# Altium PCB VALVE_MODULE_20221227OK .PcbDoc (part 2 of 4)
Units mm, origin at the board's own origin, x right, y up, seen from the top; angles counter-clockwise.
Board outline 260.15 x 142.01 mm, 2 copper layers (Top Layer, Bottom Layer); 455 components, 212 nets, 1302 pads, 385 vias.
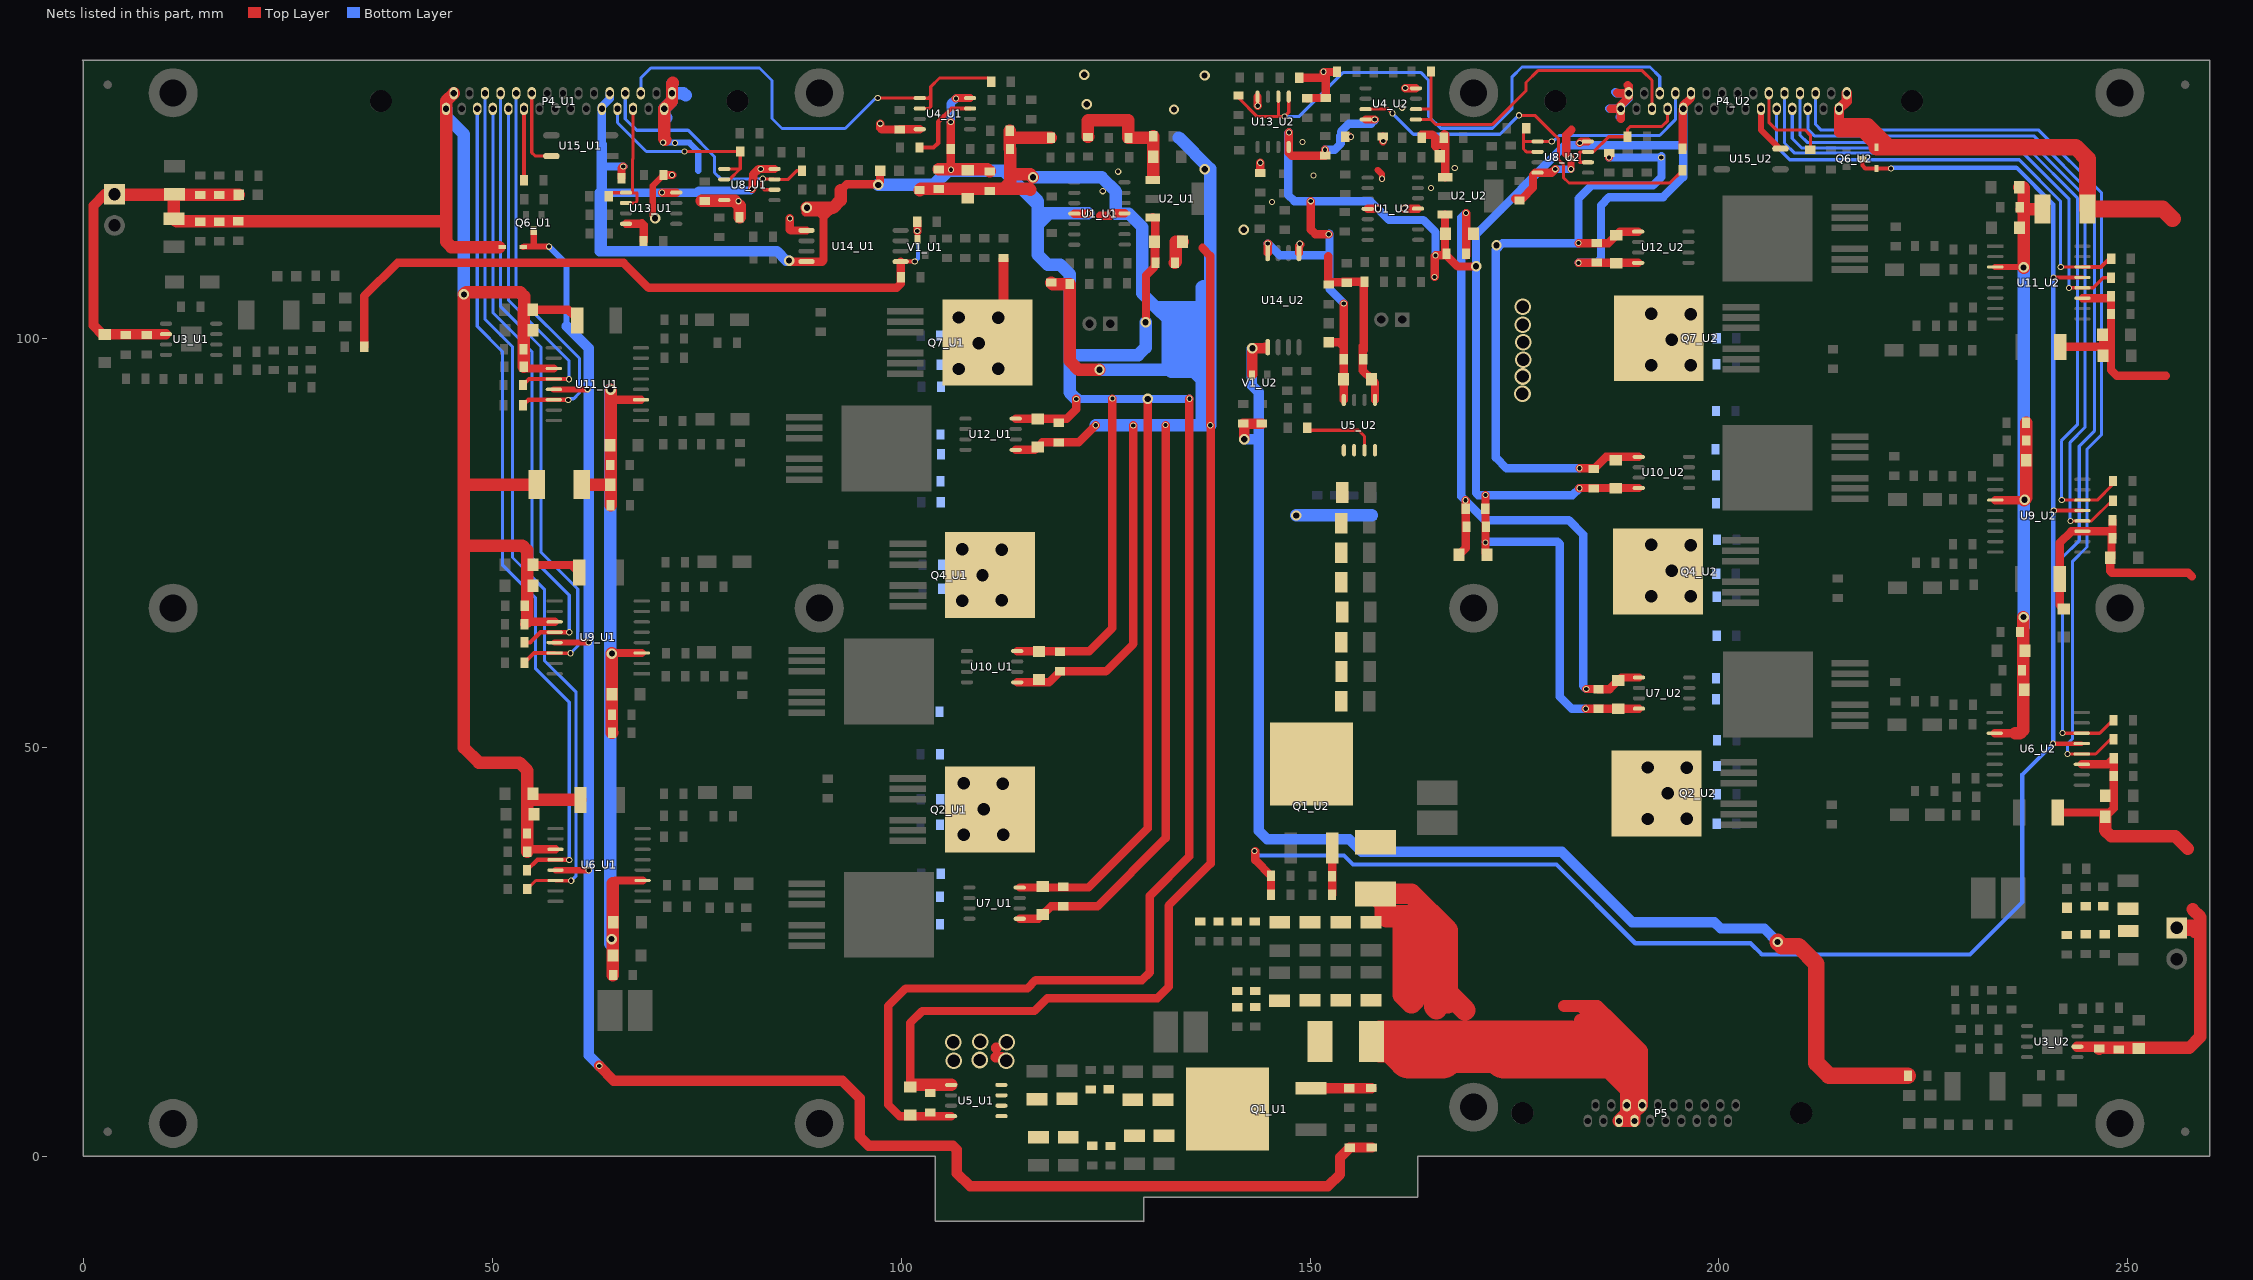
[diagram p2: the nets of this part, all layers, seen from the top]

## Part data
C1_U1 C1_U2 C2_U1 C2_U2: library part ELECTRO1, "Electrolytic Capacitor"
C3_U1 C3_U2 C4_U1 C4_U2 C12_U1 C12_U2 C14_U1 C14_U2 C31_U1 C31_U2 C32_U1 C32_U2 C33_U1 C33_U2 C42_U1 C42_U2 C43_U1 C43_U2 C44_U1 C44_U2 C45_U1 C45_U2 C46_U1 C46_U2 C48_U1 C48_U2 C50_U1 C50_U2 C51_U1 C51_U2 C52_U1 C52_U2 C53_U1 C53_U2 C61_U1 C61_U2 C64_U1 C64_U2 C67_U1 C67_U2 C68_U1 C68_U2 C73_U1 C73_U2 C74_U1 C74_U2 C75_U1 C75_U2 C76_U1 C76_U2 C77_U1 C77_U2 C78_U1 C78_U2 C79_U1 C79_U2 C80_U1 C80_U2 C81_U1 C81_U2 C82_U1 C82_U2 C83_U1 C83_U2 C84_U1 C84_U2 C85_U1 C85_U2 C86_U1 C86_U2 C87_U1 C87_U2 C88_U1 C88_U2 C89_U1 C89_U2 C90_U1 C90_U2 C91_U1 C91_U2 C92_U1 C92_U2 C93_U1 C93_U2 C95 C96 C97 C98 C99 C100 C101 C102 C103_U1 C103_U2 C107_U1 C107_U2 C109_U1 C109_U2 C111_U1 C111_U2 C113_U1 C113_U2: library part CAP, "Capacitor"
C5_U1 C5_U2 C6_U1 C6_U2 C24_U1 C24_U2 C41_U1 C41_U2 C49_U1 C49_U2 C55_U1 C55_U2 C56_U1 C56_U2 C57_U1 C57_U2 C66_U1 C66_U2 C72_U1 C72_U2 C104_U1 C104_U2 C106_U1 C106_U2 C108_U1 C108_U2 C110_U1 C110_U2 C112_U1 C112_U2: library part Cap2, "Capacitor"
C7_U1 C7_U2 C8_U1 C8_U2 C9_U1 C9_U2 C10_U1 C10_U2 C11_U1 C11_U2 C13_U1 C13_U2 C23_U1 C23_U2 C25_U1 C25_U2 C29_U1 C29_U2 C30_U1 C30_U2 C58_U1 C58_U2 C59_U1 C59_U2 C60_U1 C60_U2 C69_U1 C69_U2 C105_U1 C105_U2: library part "Cap Semi", "Capacitor (Semiconductor SIM Model)"
C15_U1 C15_U2 C16_U1 C16_U2 C17_U1 C17_U2 C18_U1 C18_U2 C19_U1 C19_U2 C20_U1 C20_U2 C34 C35 C36 C37 C38 C39 C40 C70_U1 C70_U2 C71_U1 C71_U2 C94: library part "Cap Pol1", "Polarized Capacitor (Radial)"
C21_U1 C21_U2 C22_U1 C22_U2 C65_U1 C65_U2: library part CAP1
C26_U1 C26_U2 C27_U1 C27_U2 C28_U1 C28_U2: library part Cap, "Capacitor"
C47_U1 C47_U2 C54_U1 C54_U2: "Capacitor (Semiconductor SIM Model)"
C62_U1 C62_U2 C63_U1 C63_U2: library part CAP
D1_U1 D1_U2: library part LED2
D2_U1 D2_U2 D5_U1 D5_U2 D9_U1 D9_U2 D10_U1 D10_U2 D14_U1 D14_U2 D15_U1 D15_U2 D18_U1 D18_U2: library part "DIODE SCHOTTKY", "Schottky Diode"
D3_U1 D3_U2 D19_U1 D19_U2: library part LED0, "Typical INFRARED GaAs LED"
D6_U1 D6_U2 D8_U1 D8_U2 D11_U1 D11_U2 D16_U1 D16_U2: library part Diode, "Default Diode"
F1 F2: library part "Fuse 2", "Fuse"
L1_U1 L1_U2 L2_U1 L2_U2: library part Inductor, "Inductor"
P1_U1 P1_U2 P2_U1 P2_U2: "Header, 2-Pin"
P4_U1 P4_U2: "Header, 15-Pin, Dual row"
P5: "Header, 10-Pin, Dual row"
Q1_U1 Q1_U2: library part MOSFET-P, "P-Channel MOSFET"
Q2_U1 Q2_U2 Q3_U1 Q3_U2 Q4_U1 Q4_U2 Q5_U1 Q5_U2 Q7_U1 Q7_U2 Q8_U1 Q8_U2: library part IPB160N04S3-H2
R1_U1 R1_U2 R2_U1 R2_U2 R3_U1 R3_U2 R4_U1 R4_U2 R5_U1 R5_U2 R6_U1 R6_U2 R7_U1 R7_U2 R8_U1 R8_U2 R9_U1 R9_U2 R10_U1 R10_U2 R11_U1 R11_U2 R12_U1 R12_U2 R13_U1 R13_U2 R14_U1 R14_U2 R15_U1 R15_U2 R18_U1 R18_U2 R21_U1 R21_U2 R23_U1 R23_U2 R26_U1 R26_U2 R27_U1 R27_U2 R28_U1 R28_U2 R29_U1 R29_U2 R30_U1 R30_U2 R32_U1 R32_U2 R34_U1 R34_U2 R35_U1 R35_U2 R36_U1 R36_U2 R37_U1 R37_U2 R38_U1 R38_U2 R39_U1 R39_U2 R41_U1 R41_U2 R42_U1 R42_U2 R43_U1 R43_U2 R44_U1 R44_U2 R47_U1 R47_U2 R49_U1 R49_U2 R52_U1 R52_U2 R53_U1 R53_U2 R54_U1 R54_U2 R56_U1 R56_U2 R57_U1 R57_U2 R59_U1 R59_U2 R60_U1 R60_U2 R61_U1 R61_U2 R62_U1 R62_U2 R64_U1 R64_U2 R66_U1 R66_U2 R67_U1 R67_U2 R68_U1 R68_U2 R69_U1 R69_U2 R70_U1 R70_U2 R72_U1 R72_U2 R73_U1 R73_U2 R74_U1 R74_U2 R75_U1 R75_U2 R76_U1 R76_U2 R77_U1 R77_U2 R78_U1 R78_U2 R79 R80: library part Res2, "Resistor"
R16_U1 R16_U2 R17_U1 R17_U2 R19_U1 R19_U2 R20_U1 R20_U2 R22_U1 R22_U2 R24_U1 R24_U2 R25_U1 R25_U2 R31_U1 R31_U2 R33_U1 R33_U2 R40_U1 R40_U2 R45_U1 R45_U2 R46_U1 R46_U2 R48_U1 R48_U2 R50_U1 R50_U2 R55_U1 R55_U2 R58_U1 R58_U2 R63_U1 R63_U2 R65_U1 R65_U2 R71_U1 R71_U2: library part RES
U1_U1 U1_U2: library part TL084D, "JFET-Input Operational Amplifier"
U2_U1 U2_U2: library part AS1117
U4_U1 U4_U2 U8_U1 U8_U2 U13_U1 U13_U2: library part LT1358, "Fast Settling Dual Operational Amplifier"
U5_U1 U5_U2 U7_U1 U7_U2 U10_U1 U10_U2 U12_U1 U12_U2: library part ACS711
U15_U1 U15_U2: library part TLP521-1

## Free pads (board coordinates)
  round 1.016 smd: ""(3,3) ""(3,131) ""(257,3) ""(257,131)
  round 1.016 smd far side: ""(3,3) ""(3,131) ""(257,3) ""(257,131)
  round 6 hole 3.3: ""(11,4) ""(11,67) ""(11,130) ""(90,4) ""(90,67) ""(90,130) ""(170,6) ""(170,67) ""(170,130) ""(249,4) ""(249,67) ""(249,130)

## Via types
v1: diameter 0.762, hole 0.508, Top Layer to Bottom Layer, 142 vias
v2: diameter 2.032, hole 1.524, Top Layer to Bottom Layer, 140 vias
v3: diameter 1.27, hole 0.762, Top Layer to Bottom Layer, 77 vias
v4: diameter 1.27, hole 0.711, Top Layer to Bottom Layer, 14 vias
v5: diameter 1.778, hole 1.27, Top Layer to Bottom Layer, 12 vias

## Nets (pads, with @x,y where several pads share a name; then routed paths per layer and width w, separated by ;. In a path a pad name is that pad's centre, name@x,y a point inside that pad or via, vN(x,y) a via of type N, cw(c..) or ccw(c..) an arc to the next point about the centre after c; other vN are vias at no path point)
1PWM1_U1: P4_U1.3 R31_U1.1 U6_U1.12 | length 102.2
  Top Layer w0.508: R31_U1.1@54.28,34.976 55.55,36.246 U6_U1.12@57.752,36.246 59.461,36.246 v1(59.436,36.22)
  Bottom Layer w0.381: P4_U1.3@48.184,128.047 48.184,101.447 51.257,98.374 51.257,72.314 55.296,68.275 55.296,59.639 59.436,55.499 v1(59.436,36.22)
1PWM1_U2: P4_U2.3 R31_U2.1 U6_U2.12 | length 118.9
  Top Layer w0.381: v1(242.621,49.174) U6_U2.12@244.355,49.174 246.05,49.174 247.828,50.952 R31_U2.1@248.234,50.952
  Bottom Layer w0.381: P4_U2.3@211.813,129.952 211.813,126.134 212.496,125.451 239.09,125.451 246.786,117.754 246.786,88.24 244.983,86.436 244.983,74.473 243.205,72.695 243.205,51.003 242.621,50.419 v1(242.621,49.174)
1PWM2_U1: P4_U1.18 R33_U1.1 U6_U1.14 | length 106.9
  Top Layer w0.381: R33_U1.1@54.305,32.664 55.347,33.706 U6_U1.14@57.752,33.706 57.778,33.68 v1(59.665,33.68)
  Bottom Layer w0.381: P4_U1.18@49.136,129.952 49.137,102.324 52.502,98.958 52.502,73.203 56.388,69.317 56.388,60.604 60.274,56.718 60.274,34.29 v1(59.665,33.68)
1PWM2_U2: P4_U2.18 R33_U2.1 U6_U2.14 | length 115.1
  Top Layer w0.381: v1(241.986,51.74) 242.011,51.714 U6_U2.14@244.355,51.714 246.532,51.714 248.133,53.315 R33_U2.1@248.234,53.315
  Bottom Layer w0.381: P4_U2.18@210.861,128.047 210.861,125.537 211.658,124.739 238.481,124.739 245.897,117.323 245.897,88.646 244.043,86.792 244.043,75.26 241.986,73.203 v1(241.986,51.74)
1PWM3_U1: P4_U1.4 R48_U1.1 U9_U1.12 | length 73.9
  Top Layer w0.508: R48_U1.1@53.95,62.814 54.661,62.814 55.905,64.059 U9_U1.12@57.651,64.059 v1(59.436,64.059)
  Bottom Layer w0.381: P4_U1.4@50.089,128.047 50.089,103.149 54.864,98.374 54.864,73.152 59.436,68.58 v1(59.436,64.059)
1PWM3_U2: P4_U2.4 R48_U2.1 U9_U2.12 | length 89.7
  Top Layer w0.381: v1(242.976,77.673) U9_U2.12@244.432,77.673 245.542,77.673 247.98,80.112 R48_U2.1@248.158,80.112
  Bottom Layer w0.381: P4_U2.4@209.908,129.952 209.908,124.813 210.769,123.952 238.15,123.952 244.754,117.348 244.754,89.103 242.926,87.274 242.926,77.724 v1(242.976,77.673)
1PWM4_U1: P4_U1.19 R50_U1.1 U9_U1.14 | length 78.9
  Top Layer w0.381: U9_U1.14@57.651,61.519 57.676,61.493 v1(59.588,61.493)
  Top Layer w0.508: R50_U1.1@53.95,60.35 55.118,61.519 U9_U1.14@57.651,61.519
  Bottom Layer w0.381: P4_U1.19@51.041,129.952 51.042,103.873 55.982,98.933 55.982,73.838 60.477,69.342 60.477,62.382 v1(59.588,61.493)
1PWM4_U2: P4_U2.19 R50_U2.1 U9_U2.14 | length 86.7
  Top Layer w0.381: v1(241.91,80.239) 244.406,80.239 U9_U2.14@244.432,80.213 246.253,80.213 248.158,82.118 R50_U2.1@248.158,82.55
  Bottom Layer w0.381: P4_U2.19@208.956,128.047 208.956,124.419 210.109,123.266 237.719,123.266 243.815,117.17 243.815,89.408 241.859,87.452 241.859,80.289 v1(241.91,80.239)
1PWM5_U1: P4_U1.5 R63_U1.1 U11_U1.12 | length 42.1
  Top Layer w0.508: R63_U1.1@53.772,94.285 54.508,95.021 U11_U1.12@57.549,95.021 59.385,95.021 v1(59.411,94.996)
  Bottom Layer w0.381: P4_U1.5@51.994,128.047 51.994,104.673 59.411,97.257 v1(59.411,94.996)
1PWM5_U2: P4_U2.5 R63_U2.1 U11_U2.12 | length 60.2
  Top Layer w0.381: v1(242.799,106.147) 242.824,106.172 U11_U2.12@244.432,106.172 245.77,106.172 246.99,107.391 R63_U2.1@247.929,107.391
  Bottom Layer w0.381: P4_U2.5@208.003,129.952 208.003,123.873 209.245,122.631 237.211,122.631 242.773,117.069 242.773,106.172 v1(242.799,106.147)
1PWM6_U1: P4_U1.20 R65_U1.1 U11_U1.14 | length 47.4
  Top Layer w0.508: R65_U1.1@53.772,91.821 54.432,92.481 U11_U1.14@57.549,92.481 59.284,92.481 v1(59.309,92.456)
  Bottom Layer w0.381: P4_U1.20@52.946,129.952 52.947,105.27 60.681,97.536 60.681,93.32 59.969,92.608 59.461,92.608 v1(59.309,92.456)
1PWM6_U2: P4_U2.20 R65_U2.1 U11_U2.14 | length 56.8
  Top Layer w0.381: v1(241.783,108.712) U11_U2.14@244.432,108.712
  Top Layer w0.508: U11_U2.14@244.432,108.712 246.71,108.712 247.701,109.703 R65_U2.1@247.955,109.703
  Bottom Layer w0.381: P4_U2.20@207.051,128.047 207.051,123.403 208.636,121.818 236.703,121.818 241.732,116.789 241.732,108.712 v1(241.783,108.712)
+5VA_U1: C1_U1.1 C4_U1.1 C55_U1.1 C56_U1.1 C57_U1.1 C58_U1.2 C59_U1.2 C60_U1.2 C62_U1.1 C63_U1.1 C65_U1.1 C104_U1.1 C105_U1.2 D19_U1.1 P4_U1.11 P4_U1.26 R13_U1.2 R45_U1.1 U1_U1.4 U2_U1.3 U4_U1.8 U5_U1.8 U7_U1.8 U8_U1.8 U10_U1.8 U12_U1.8 U13_U1.8 U14_U1.8 | length 473.5
  Top Layer w1.016: R45_U1.1@65.811,119.558 65.811,120.802 66.015,121.006 v1(66.04,121.006) ; v1(70.79,117.805) U13_U1.8@72.517,117.805 ; v1(81.788,118.237) 81.839,118.288 81.839,119.278 81.928,119.366 81.928,120.028 82.601,120.701 v1(82.855,120.701) U8_U1.8@84.531,120.701 ; v3(86.309,109.499) 86.309,109.347 86.335,109.372 U14_U1.8@88.443,109.372 90.373,109.372 90.526,109.525 90.526,114.808 ; v3@88.316,115.392 88.341,115.367 90.043,115.367 90.526,114.884 90.526,114.808 ; 91.669,115.951 90.526,114.808 ; 92.608,118.085 93.345,118.821 97.13,118.821 97.434,119.126 D19_U1.1@97.434,120.472 ; v1(106.07,126.441) R13_U1.2@106.07,123.139 106.07,120.65 106.07,120.625 v1(106.096,120.599) ; U5_U1.8@106.121,4.902 99.822,4.902 98.425,6.299 98.425,18.364 100.571,20.511 115.456,20.511 116.459,21.514 129.464,21.514 130.404,22.454 130.404,31.826 135.23,36.652 v1@135.23,92.608 ; v1(106.705,129.311) 106.756,129.362 U4_U1.8@108.433,129.362 ; U12_U1.8@114.021,90.17 120.269,90.17 121.412,91.313 v1(121.412,92.583) v1@121.412,92.634 ; U10_U1.8@114.198,61.747 123.012,61.747 125.832,64.567 v1(125.832,92.634) ; U7_U1.8@114.503,32.842 122.936,32.842 130.15,40.056 v3(130.15,92.583) ; U1_U1.4@121.183,115.24 122.834,115.24 v1(122.86,115.265) ; v3(129.896,101.956) 129.946,102.006 129.946,107.696 130.988,108.737 C1_U1.1@130.988,111.785 ; U2_U1.3@130.759,114.783 131.089,114.452 C4_U1.1@131.089,109.245
  Top Layer w1.524: v3(88.494,115.951) 91.669,115.951 92.608,116.891 92.608,118.085 ; C63_U1.1@104.623,120.65 106.07,120.65 110.566,120.65 C59_U1.2@110.82,120.396
  Bottom Layer w1.016: 63.17,117.805 63.424,117.805 v1(70.79,117.805) 75.006,117.805 75.26,118.059 81.61,118.059 v1(81.788,118.237) ; 63.424,121.158 63.424,121.328 63.747,121.006 v1(66.04,121.006) ; 63.424,123.672 P4_U1.11@63.424,128.047 63.424,128.321 64.376,129.273 P4_U1.26@64.376,129.952 ; v1(106.07,126.441) 106.07,128.676 v1(106.705,129.311) ; v1(121.412,92.583) v3@129.921,92.583 ; v3@129.946,92.608 v3@129.921,92.583 ; v1(135.255,92.608) 135.23,92.583 v3@129.921,92.583
  Bottom Layer w1.27: 63.17,117.805 63.17,110.617 ; 63.424,121.158 63.424,117.805 63.424,110.871 63.17,110.617 ; 63.424,121.328 63.424,123.672 ; v3(86.309,109.499) 85.954,109.499 84.836,110.617 63.17,110.617
  Bottom Layer w1.524: v3(97.206,118.745) 103.988,118.745 105.715,120.472 112.573,120.472 115.646,117.399 ; v1(121.412,92.583) 120.599,93.396 120.599,97.942 ; v1(122.86,115.265) 118.11,115.265 ; v3(129.896,101.956) 129.896,98.857 128.981,97.942 120.599,97.942 ; 115.646,117.399 116.103,117.399 116.738,116.764 116.738,116.307 ; 115.646,117.399 116.738,116.307 ; 116.738,113.894 118.11,115.265 ; 116.738,113.894 116.738,110.185 117.958,108.966 119.482,108.966 120.599,107.848 120.599,97.942 ; 116.738,113.894 116.738,115.494 ; 116.738,115.494 116.967,115.265 118.11,115.265 ; 116.738,115.494 116.738,116.307
+5VA_U2: C1_U2.1 C4_U2.1 C55_U2.1 C56_U2.1 C57_U2.1 C58_U2.2 C59_U2.2 C60_U2.2 C62_U2.1 C63_U2.1 C65_U2.1 C104_U2.1 C105_U2.2 D19_U2.1 P4_U2.11 P4_U2.26 R13_U2.2 R45_U2.1 U1_U2.4 U2_U2.3 U4_U2.8 U5_U2.8 U7_U2.8 U8_U2.8 U10_U2.8 U12_U2.8 U13_U2.8 U14_U2.8 | length 273.9
  Top Layer w1.016: U14_U2.8@144.831,110.414 v1(144.831,111.582) ; v1@144.831,111.557 v1@144.907,111.557 ; v1(147.422,125.171) 147.396,125.146 U13_U2.8@147.396,123.393 147.396,122.682 147.752,122.326 R13_U2.2@151.841,122.326 v1(151.841,123.038) ; v1(150.089,116.764) 150.089,113.284 150.647,112.725 v1(152.298,112.725) ; D19_U2.1@152.298,99.517 153.543,99.517 154.127,98.933 ; U5_U2.8@154.127,92.456 C59_U2.2@154.127,97.434 154.127,98.933 ; v1(154.127,104.242) 154.127,98.933 ; U4_U2.8@156.794,126.746 v1(157.912,126.746) ; U1_U2.4@157.048,115.824 v1(158.293,115.824) ; v1(165.227,107.493) 165.252,107.518 165.252,110.058 v1(165.329,110.134) C4_U2.1@166.675,110.134 ; U2_U2.3@166.497,115.113 166.497,110.312 C4_U2.1@166.675,110.134 ; v3@170.015,108.763 168.046,108.763 C4_U2.1@166.675,110.134 ; v1(171.45,80.848) v1(171.45,75.032) 171.45,73.736 C55_U2.1@171.653,73.533 ; v1(182.829,109.22) U12_U2.8@190.119,109.22 ; v1(182.931,81.661) 182.956,81.686 U10_U2.8@190.195,81.686 ; v1(182.982,123.876) 183.159,124.054 U8_U2.8@183.972,124.054 ; v1(183.718,54.712) C105_U2.2@185.268,54.712 C104_U2.1@187.681,54.712 U7_U2.8@190.221,54.712 ; R45_U2.1@195.555,123.165 195.555,127.981 P4_U2.26@195.621,128.047 195.621,128.438 196.573,129.39 P4_U2.11@196.573,129.952
  Bottom Layer w1.016: v1@144.844,111.595 146.304,110.134 152.375,110.134 ; v1(147.422,125.171) 147.32,125.07 147.32,117.526 148.082,116.764 v1(150.089,116.764) 157.353,116.764 v1(158.293,115.824) 159.664,114.452 163.855,114.452 165.329,112.979 v1(165.329,110.134) ; v1(151.841,123.038) 153.01,123.038 153.67,123.698 ; v1@152.349,112.776 152.375,112.751 152.375,110.134 ; 153.67,124.739 153.67,123.698 ; v1(154.127,104.242) 152.375,105.994 152.375,110.134 ; v1@157.912,126.682 157.467,126.238 154.762,126.238 153.784,125.26 153.784,123.812 153.67,123.698 ; v1@171.45,75.133 180.264,75.133 180.543,74.854 180.543,56.159 181.991,54.712 v1(183.718,54.712) ; v1(182.829,109.22) 185.064,109.22 185.572,109.728 185.572,116.256 186.563,117.246 193.167,117.246 195.621,119.7 195.621,123.901 ; v1(182.931,81.661) 182.093,80.823 170.536,80.823 170.282,81.077 170.282,112.7 181.178,123.596 195.316,123.596 195.621,123.901 ; P4_U2.26@195.621,128.047 195.621,123.901
  other v3: 170.307,108.814
AGND_U1: C1_U1.2 C2_U1.2 C3_U1.2 C4_U1.2 C12_U1.2 C14_U1.2 C33_U1.2 C46_U1.2 C53_U1.2 C55_U1.2 C56_U1.2 C57_U1.2 C58_U1.1 C59_U1.1 C60_U1.1 C62_U1.2 C63_U1.2 C64_U1.2 C65_U1.2 C104_U1.2 C105_U1.1 P4_U1.15 P4_U1.30 R9_U1.1 R10_U1.1 R11_U1.2 R12_U1.2 R14_U1.1 R71_U1.1 R72_U1.2 U1_U1.11 U2_U1.1 U4_U1.4 U5_U1.5 U7_U1.5 U8_U1.4 U10_U1.5 U12_U1.5 U13_U1.4 U14_U1.5 | length 527.7
  Top Layer w0.762: v3(69.926,114.681) 69.647,114.96 69.647,118.643 C64_U1.2@70.968,119.964
  Top Layer w1.016: U13_U1.4@66.37,113.995 68.275,113.995 68.326,114.046 68.529,113.843 R72_U1.2@68.529,111.887 ; C64_U1.2@70.968,119.964 v1(72.009,119.964) ; v1(86.411,114.656) 86.411,113.284 86.512,113.182 U14_U1.5@88.443,113.182 ; v1(97.46,126.238) 97.46,125.705 97.638,125.527 C33_U1.2@99.822,125.527 99.847,125.552 U4_U1.4@102.286,125.552 ; C104_U1.2@101.117,8.458 101.117,16.281 102.591,17.755 116.307,17.755 117.881,19.329 131.343,19.329 132.715,20.701 132.715,30.632 137.846,35.763 v1@137.846,89.357 ; U12_U1.5@114.021,86.36 116.357,86.36 C55_U1.2@116.713,86.716 117.272,87.274 C62_U1.2@119.278,87.274 121.717,87.274 v1(123.8,89.357) ; U10_U1.5@114.198,57.937 118.085,57.937 C58_U1.1@119.431,59.284 125.044,59.284 128.397,62.636 v1@128.397,89.357 ; U7_U1.5@114.503,29.032 116.815,29.032 C65_U1.2@117.323,29.54 118.339,30.556 C60_U1.1@119.837,30.556 124.028,30.556 132.359,38.887 v1@132.359,89.357 ; 124.333,114.986 125.552,114.986 v1(125.806,115.24) ; v1@125.654,115.24 125.679,115.265 U1_U1.11@127.33,115.265 ; 136.855,111.049 136.855,111.023 137.795,110.084 v1(137.795,89.357)
  Top Layer w1.524: 71.196,124.257 71.044,124.409 P4_U1.15@71.044,128.047 71.996,128.999 P4_U1.30@71.996,129.952 71.996,131.127 72.085,131.216 ; C46_U1.2@75.641,116.789 79.654,116.789 80.264,116.18 C53_U1.2@80.264,114.783 ; C104_U1.2@101.219,8.712 U5_U1.5@106.121,8.712 ; R71_U1.1@102.26,118.11 102.413,118.262 C63_U1.2@104.623,118.262 112.547,118.262 ; C14_U1.2@113.284,125.374 113.284,124.409 ; 115.799,118.135 115.672,118.262 112.547,118.262 ; v3(116.129,119.685) 115.773,120.04 113.335,120.04 ; R9_U1.1@118.313,124.511 113.386,124.511 113.284,124.409 ; R10_U1.1@118.364,106.807 118.542,106.629 R11_U1.2@120.625,106.629 120.625,97.231 121.717,96.139 v3(124.257,96.139) ; C12_U1.2@122.86,124.612 122.809,124.663 122.809,126.594 122.885,126.67 127.762,126.67 127.787,126.644 R12_U1.2@127.787,124.485 130.632,124.485 C3_U1.2@130.835,124.689 C2_U1.2@130.835,122.199 U2_U1.1@130.835,119.71 ; C4_U1.2@133.477,109.245 133.604,109.372 133.604,111.811 133.629,111.785 C1_U1.2@134.417,111.785 ; 112.547,118.262 113.335,119.05 113.335,120.04 ; 113.284,124.409 113.284,123.19 R14_U1.1@113.335,123.139 113.335,120.04
  Bottom Layer w0.762: v1(70.917,123.927) 74.105,123.927 75.209,122.822 75.209,120.472
  Bottom Layer w1.016: v1(125.806,115.24) 126.263,115.24
  Bottom Layer w1.524: 71.323,126.949 71.044,127.228 P4_U1.15@71.044,128.047 71.996,128.999 P4_U1.30@71.996,129.952 ; 72.06,131.166 71.996,131.102 P4_U1.30@71.996,129.952 ; 73.66,129.692 73.4,129.952 P4_U1.30@71.996,129.952 ; v3@116.129,119.659 124.536,119.659 126.263,117.932 126.263,115.24 127.838,115.24 129.489,113.589 129.489,105.486 131.191,103.784 ; v1(123.8,89.357) 136.627,89.357 ; v3(124.257,96.139) 132.817,96.139 ; 133.96,124.536 137.795,120.701 v1(137.795,89.357) 136.627,89.357 ; 136.931,106.375 136.779,106.223 136.779,94.869 ; 131.191,103.784 133.172,103.784 ; 131.191,103.784 132.613,102.362 132.613,96.342 132.817,96.139 ; 132.817,96.139 133.045,95.91 ; 133.045,95.91 133.045,103.657 133.172,103.784 ; 133.045,95.91 134.442,95.91 ; 133.172,103.784 134.468,103.784 ; 134.442,95.91 135.738,95.91 ; 134.442,95.91 134.442,103.759 134.468,103.784 ; 134.468,103.784 135.788,103.784 135.738,103.734 135.738,95.91 ; 135.738,95.91 136.779,94.869 ; 136.627,89.357 136.779,89.51 136.779,94.869
  other v1: 128.397,89.332 132.334,89.383 80.112,116.764 124.663,117.983 126.543,120.371 72.365,123.876
  other v3: 137.135,120.65 133.375,127.965 122.707,128.6 137.109,132.131 122.403,132.207
AGND_U2: C1_U2.2 C2_U2.2 C3_U2.2 C4_U2.2 C12_U2.2 C14_U2.2 C33_U2.2 C46_U2.2 C53_U2.2 C55_U2.2 C56_U2.2 C57_U2.2 C58_U2.1 C59_U2.1 C60_U2.1 C62_U2.2 C63_U2.2 C64_U2.2 C65_U2.2 C104_U2.2 C105_U2.1 P4_U2.15 P4_U2.30 R9_U2.1 R10_U2.1 R11_U2.2 R12_U2.2 R14_U2.1 R71_U2.1 R72_U2.2 U1_U2.11 U2_U2.1 U4_U2.4 U5_U2.5 U7_U2.5 U8_U2.4 U10_U2.5 U12_U2.5 U13_U2.4 U14_U2.5 | length 258.7
  Top Layer w0.762: 158.293,120.574 158.801,120.066 v1(158.801,119.507)
  Top Layer w0.889: v1(181.915,120.675) v1@181.915,121.945
  Top Layer w1.016: U13_U2.4@143.586,129.54 143.586,128.448 v1(143.612,128.422) ; v1(143.909,121.456) 143.916,121.448 R72_U2.2@143.916,120.218 ; U14_U2.5@148.641,110.414 148.641,111.277 v1@148.819,111.455 ; C64_U2.2@148.692,131.851 151.587,131.851 151.917,132.182 ; C14_U2.2@149.682,129.337 149.708,129.362 R14_U2.1@151.917,129.362 151.917,132.182 ; v1@151.689,132.563 152.298,132.563 ; 152.222,110.007 152.222,107.264 152.654,106.832 153.924,106.832 154,106.909 156.159,106.909 156.566,106.502 156.566,98.527 156.439,98.4 ; C33_U2.2@153.289,132.563 152.298,132.563 ; R9_U2.1@154.28,124.663 v1@154.813,124.663 ; 156.413,99.06 156.439,99.035 156.439,98.4 ; U5_U2.5@157.937,92.456 157.937,94.564 C57_U2.2@157.505,94.996 156.439,96.063 156.439,98.4 ; v1@158.928,124.104 C12_U2.2@158.928,124.663 ; v1(161.519,115.849) U1_U2.11@163.195,115.849 ; v1(161.646,130.581) 161.671,130.556 U4_U2.4@162.941,130.556 ; R12_U2.2@163.627,124.892 164.948,124.892 165.303,124.536 165.303,123.495 165.379,123.419 165.583,123.622 166.421,123.622 ; C3_U2.2@166.421,124.968 166.522,124.866 U2_U2.1@166.522,119.685 ; C55_U2.2@168.224,73.533 169.037,74.346 C62_U2.2@169.037,79.172 169.037,80.162 v1(169.012,80.188) ; v1(169.062,115.316) 169.088,115.291 C4_U2.2@169.088,110.109 ; C46_U2.2@175.057,117.043 175.895,117.043 177.267,118.415 177.267,119.964 177.546,120.244 U8_U2.4@177.825,120.244 179.553,120.244 v1(179.984,120.675) ; v1@181.915,121.945 181.331,122.53 181.331,124.841 181.966,125.476 ; v1(182.829,111.633) C58_U2.1@185.039,111.633 186.487,111.633 C56_U2.2@187.452,112.598 187.884,113.03 U12_U2.5@190.119,113.03 ; v1(182.956,84.099) 184.633,84.099 C63_U2.2@184.709,84.023 186.182,85.496 U10_U2.5@190.195,85.496 ; v1(183.769,57.125) C105_U2.1@185.242,57.125 ; C105_U2.1@185.268,57.099 186.639,57.099 C104_U2.2@187.681,58.141 188.062,58.522 U7_U2.5@190.221,58.522 ; v1(186.563,122.098) C53_U2.2@186.563,122.657 ; 186.741,128.041 187.995,128.041 P4_U2.30@188.001,128.047 ; 187.579,129.997 187.624,129.952 P4_U2.15@188.953,129.952 ; 188.011,126.797 188.001,126.807 P4_U2.30@188.001,128.047 ; 188.826,130.958 188.953,130.831 P4_U2.15@188.953,129.952 ; 151.917,132.182 152.298,132.563 ; P4_U2.30@188.001,128.047 188.001,128.514 188.953,129.466 P4_U2.15@188.953,129.952
  Bottom Layer w0.889: v1(179.984,120.675) v1(181.915,120.675)
  Bottom Layer w1.016: v1(169.062,115.316) 168.504,114.757 168.504,80.645 171.399,77.749 181.635,77.749 183.388,75.997 183.388,57.506 v1(183.769,57.125) ; v1(182.956,84.099) 174.015,84.099 172.72,85.395 172.72,110.82 173.533,111.633 v1(182.829,111.633) 182.829,117.094 184.404,118.669 191.922,118.669 192.964,119.71 192.964,122.276 192.786,122.098 v1(186.563,122.098) ; 186.588,128.092 186.634,128.047 P4_U2.30@188.001,128.047 ; 187.3,130.099 187.446,129.952 P4_U2.15@188.953,129.952 188.953,129.339 188.001,128.387 P4_U2.30@188.001,128.047 ; 187.874,127.041 188.001,127.168 P4_U2.30@188.001,128.047
  other v1: 148.742,111.557 145.364,116.662 164.795,118.364 150.419,119.888 167.691,120.802 181.864,122.047 192.938,122.098 149.073,124.003 158.953,124.104 155.016,124.638 161.265,128.194 151.663,132.588
  other v3: 172.796,111.379 141.91,113.259
EN_WRK_U1: P4_U1.6 R55_U1.2 | length 9
  Top Layer w0.508: R55_U1.2@53.899,119.024 P4_U1.6@53.899,128.047
EN_WRK_U2: P4_U2.6 R55_U2.2 | length 11.1
  Top Layer w0.381: P4_U2.6@206.098,129.952 206.098,126.39 207.013,125.476 210.515,125.476 211.176,124.816 211.176,123.063 R55_U2.2@211.15,123.038
ENWRK_U1: D8_U1.1 Q6_U1.3 R18_U1.2 R38_U1.2 U6_U1.13 U9_U1.13 U11_U1.13 | length 228.3
  Top Layer w0.762: D8_U1.1@53.823,111.151 53.899,111.227 55.093,111.227 ; Q6_U1.3@55.093,113.132 55.093,111.227 ; v1(56.972,111.201) 56.947,111.227 55.093,111.227 ; U11_U1.13@57.549,93.751 61.646,93.751 v1(61.671,93.777) ; U9_U1.13@57.651,62.789 v1@61.671,62.789 ; U6_U1.13@57.752,34.976 57.778,34.95 v1(61.824,34.95)
  Top Layer w1.27: v1(63.094,11.049) 64.897,9.246 92.837,9.246 94.971,7.112 94.971,2.388 96.063,1.295 106.324,1.295 106.832,0.787 106.832,-2.083 108.433,-3.683 152.171,-3.683 153.67,-2.184 153.67,-0.127 R38_U1.2@154.838,1.041 154.864,1.067 R18_U1.2@157.556,1.067
  Bottom Layer w0.762: v1(56.972,111.201) 59.106,109.068 59.106,101.473 59.157,101.422
  Bottom Layer w1.27: 59.106,101.473 61.824,98.755 v1(61.824,62.789) v1(61.824,34.95) 61.824,12.319 v1(63.094,11.049)
ENWRK_U2: D8_U2.1 Q6_U2.3 R18_U2.2 R38_U2.2 U6_U2.13 U9_U2.13 U11_U2.13 | length 231.5
  Top Layer w0.508: Q6_U2.3@217.526,121.92 217.526,121.107 217.881,120.752 D8_U2.1@219.278,120.752 v1(221.031,120.752) ; v1(240.843,50.419) 244.33,50.419 U6_U2.13@244.355,50.444 ; v1(240.894,107.442) U11_U2.13@244.432,107.442 ; v1(240.919,78.943) U9_U2.13@244.432,78.943
  Top Layer w1.016: v1@143.307,37.313 143.307,36.195 R18_U2.2@145.237,34.265 R38_U2.2@145.237,31.953
  Bottom Layer w0.508: v1(143.205,37.313) 143.739,36.779 154.153,36.779 155.27,35.662 180.137,35.662 189.763,26.035 203.86,26.035 205.232,24.663 230.683,24.663 237.084,31.064 237.084,46.66 v1(240.843,50.419) 240.868,50.444 240.868,116.332 236.347,120.853 v1@221.031,120.853
FAULT_U1: P4_U1.21 U15_U1.6 | length 9.8
  Top Layer w0.381: P4_U1.21@54.851,129.952 54.852,122.694 55.27,122.276 U15_U1.6@57.226,122.276
FAULT_U2: P4_U2.21 U15_U2.6 | length 5.8
  Top Layer w0.762: P4_U2.21@205.146,128.047 205.146,125.451 U15_U2.6@207.407,123.19
HVCC_IN: C34.1 C35.1 C36.1 C37.1 C38.1 C39.1 C40.1 C94.1 C95.1 C96.1 C97.1 C98.1 C99.1 C100.1 C101.1 C102.1 F1.1 F2.1 P5.7 P5.8 P5.17 P5.18 | length 203.4
  Top Layer w1.524: 181.077,18.364 185.115,18.364 187.02,16.459 ; 181.762,14.021 182.601,14.021 184.607,12.014 188.665,7.956 ; 183.007,16.612 183.159,16.459 185.039,16.459 ; 183.363,18.136 185.039,16.459 ; 188.798,13.818 189.617,12.998 189.617,5.271 ; 185.039,16.459 187.02,16.459 ; 187.02,16.459 190.57,12.909 190.57,6.223 189.617,5.271 ; 188.665,7.956 188.665,6.223 188.665,5.271 187.712,4.318 189.617,4.318 189.617,5.271 ; 188.665,7.956 188.665,9.404 ; 188.665,9.404 188.665,10.541 188.665,11.538 188.189,12.014 186.182,14.021 186.182,12.014 186.182,11.887 188.665,9.404
  Top Layer w2.54: 165.456,18.009 165.176,18.288 165.176,28.6 164.363,29.413 160.731,29.413 ; 166.421,20.371 168.935,17.856 ; 166.827,18.694 166.827,27.635 162.382,32.08 F2.1@157.988,32.08 159.182,30.886 159.182,29.413 ; 159.182,29.413 159.385,29.21 160.934,29.21 ; 159.182,29.413 160.731,29.413 ; 160.731,29.413 160.934,29.21 ; 160.934,29.21 161.366,28.778 161.366,19.736 162.408,18.694 162.712,18.999 162.712,29.21 160.934,29.21
  Top Layer w3.81: 166.141,12.065 173.736,12.065 180.645,12.065 182.601,14.021
  Top Layer w5.08: F1.1@158.648,14.021 160.147,14.021 ; 162.1,12.065 162.103,12.065 ; 166.141,12.065 162.103,12.065 ; 181.762,14.021 171.78,14.021 ; 182.601,14.021 186.182,14.021 ; 187.412,11.794 188.665,10.541 ; 188.57,12.014 188.189,12.014 186.182,12.014 184.607,12.014 173.787,12.014 173.736,12.065 171.78,14.021 ; 160.147,14.021 162.103,12.065 ; 160.147,14.021 171.78,14.021
HVCC_IN_U1: F1.2 Q1_U1.3 R15_U1.1 R34_U1.1 | length 7.4
  Top Layer w1.27: Q1_U1.3@150.139,8.306 150.165,8.331 R15_U1.1@157.48,8.331
HVCC_IN_U2: F2.2 Q1_U2.3 R15_U2.1 R34_U2.1 | length 5.7
  Top Layer w1.016: R15_U2.1@152.705,31.953 Q1_U2.3@152.705,37.694
HVCC_U1: C78_U1.1 C79_U1.1 C80_U1.1 C81_U1.1 C82_U1.1 C83_U1.1 C84_U1.1 C85_U1.1 C86_U1.1 C87_U1.1 C88_U1.1 C89_U1.1 C90_U1.1 C91_U1.1 C92_U1.1 C93_U1.1 Q2_U1.4 Q4_U1.4 Q7_U1.4 R74_U1.2 U5_U1.3 U5_U1.4 | length 11.7
  Top Layer w1.27: Q7_U1.4@110.566,99.466 112.522,101.422 R74_U1.2@112.522,109.576 ; 111.582,12.116 v2@112.293,12.116 ; 111.633,13.183 111.633,13.259
  other v2: 106.451,11.684 112.852,11.684 109.626,11.76 106.401,13.919 112.928,13.919 109.703,13.97 107.645,39.294 112.471,39.319 110.109,42.418 112.446,45.542 107.645,45.593 107.493,67.92 112.319,67.945 109.957,71.044 112.293,74.168 107.493,74.219 107.061,96.241 111.887,96.266 109.525,99.365 111.862,102.489 107.061,102.54
HVCC_U2: C78_U2.1 C79_U2.1 C80_U2.1 C81_U2.1 C82_U2.1 C83_U2.1 C84_U2.1 C85_U2.1 C86_U2.1 C87_U2.1 C88_U2.1 C89_U2.1 C90_U2.1 C91_U2.1 C92_U2.1 C93_U2.1 Q2_U2.4 Q4_U2.4 Q7_U2.4 R74_U2.2 U5_U2.3 U5_U2.4 | length 9.3
  Top Layer w0.381: R74_U2.2@149.352,88.748 155.931,88.748 156.667,88.011 U5_U2.3@156.667,86.309
  other v2: 191.262,41.224 196.037,41.275 193.726,44.348 196.063,47.473 191.262,47.523 191.745,68.453 196.571,68.478 194.208,71.577 196.545,74.701 191.745,74.752 175.971,93.218 175.997,95.326 191.745,96.698 196.571,96.723 176.047,97.384 176.073,99.492 194.208,99.822 175.997,101.651 196.545,102.946 191.745,102.997 175.997,103.861
HVCCIN_U1: C15_U1.1 C16_U1.1 C17_U1.1 C18_U1.1 C19_U1.1 C20_U1.1 C70_U1.1 C71_U1.1 C74_U1.1 C75_U1.1 C76_U1.1 C77_U1.1 Q1_U1.2 U5_U1.1 U5_U1.2
HVCCIN_U2: C15_U2.1 C16_U2.1 C17_U2.1 C18_U2.1 C19_U2.1 C20_U2.1 C70_U2.1 C71_U2.1 C74_U2.1 C75_U2.1 C76_U2.1 C77_U2.1 Q1_U2.2 U5_U2.1 U5_U2.2 | length 9.2
  Bottom Layer w1.524: v3(148.311,78.334) C75_U2.1@157.531,78.334
II_1_AC1_U1: C45_U1.2 P4_U1.12 U8_U1.1 U8_U1.2 | length 25.4
  Top Layer w0.381: v1(73.533,122.834) C45_U1.2@80.34,122.834 80.34,120.726 ; U8_U1.2@78.384,119.431 79.045,119.431 80.315,120.701 U8_U1.1@78.384,120.701
  Bottom Layer w0.381: P4_U1.12@65.329,128.047 65.329,126.365 68.859,122.834 69.799,122.834 v1@73.635,122.834 ; 72.847,122.834 v1(73.533,122.834)
II_1_AC1_U2: C45_U2.2 P4_U2.12 U8_U2.1 U8_U2.2 | length 27.4
  Top Layer w0.381: C45_U2.2@176.098,125.73 176.098,124.054 ; U8_U2.2@177.825,122.784 176.454,122.784 176.098,123.139 176.098,124.054 ; v1(179.553,124.054) U8_U2.1@177.825,124.054 176.098,124.054
  Bottom Layer w0.381: v1(179.553,124.054) 179.629,123.977 180.442,124.79 192.735,124.79 194.668,126.723 P4_U2.12@194.668,129.952
II_1_AC2_U1: C48_U1.2 P4_U1.27 U8_U1.6 U8_U1.7 | length 32.1
  Top Layer w0.381: U8_U1.6@84.531,118.161 83.236,118.161 83.007,118.389 83.033,118.415 83.033,119.355 83.16,119.482 84.48,119.482 U8_U1.7@84.531,119.431 86.208,119.431 87.249,120.472 C48_U1.2@87.884,120.472
  Bottom Layer w0.381: P4_U1.27@66.281,129.952 66.282,126.809 67.666,125.425 73.965,125.425 77.191,122.199 77.191,120.244 77.953,119.482 83.083,119.482 v1(83.083,119.507)
II_1_AC2_U2: C48_U2.2 P4_U2.27 U8_U2.6 U8_U2.7 | length 16.7
  Top Layer w0.381: U8_U2.6@183.972,121.514 182.931,121.514 182.931,122.784 U8_U2.7@183.972,122.784 184.658,122.784 186.512,124.638 C48_U2.2@188.824,124.638 188.824,125.578 189.128,125.882 193.015,125.882 193.716,126.584 P4_U2.27@193.716,128.047
II_1_AC3_U1: C61_U1.2 P4_U1.13 U13_U1.1 U13_U1.2 | length 17.3
  Top Layer w0.381: U13_U1.2@66.37,116.535 67.488,116.535 67.716,116.764 67.716,117.754 67.691,117.78 64.694,117.78 64.719,117.805 U13_U1.1@66.37,117.805 ; 67.158,117.881 67.158,121.818 67.234,121.895 P4_U1.13@67.234,128.047
II_1_AC3_U2: C61_U2.2 P4_U2.13 U13_U2.1 U13_U2.2 | length 77.9
  Top Layer w0.381: C61_U2.2@141.249,129.692 141.249,129.388 143.535,127.102 146.126,127.102 ; U13_U2.2@146.126,129.54 146.126,127.102 ; U13_U2.1@147.396,129.54 147.396,127.635 v1(146.888,127.127) 146.863,127.102 146.126,127.102
  Bottom Layer w0.381: v1(146.888,127.127) 148.692,127.127 154.076,132.512 163.525,132.512 164.465,131.572 164.465,127.178 165.964,125.679 ; 170.459,125.679 165.964,125.679 ; P4_U2.13@192.763,129.952 192.763,131.976 191.567,133.172 175.92,133.172 174.676,131.928 174.676,128.041 172.314,125.679 165.964,125.679
II_1_DC1_U1: C31_U1.2 P4_U1.28 U4_U1.1 U4_U1.2 | length 57.2
  Top Layer w0.381: v1(97.155,129.362) U4_U1.1@102.286,129.362 102.311,129.337 103.327,129.337 103.632,129.642 ; U4_U1.2@102.286,128.092 103.403,128.092 103.632,128.321 103.632,129.642 ; C31_U1.2@111.023,131.343 110.541,131.826 104.699,131.826 103.632,130.759 103.632,129.642
  Bottom Layer w0.381: P4_U1.28@68.186,129.952 68.186,131.813 69.418,133.045 82.702,133.045 84.226,131.521 84.226,126.873 85.446,125.654 93.167,125.654 96.876,129.362 v1(97.155,129.362)
II_1_DC1_U2: C31_U2.2 P4_U2.28 U4_U2.1 U4_U2.2 | length 44.4
  Top Layer w0.381: U4_U2.1@162.941,126.746 164.77,126.746 165.405,126.111 172.263,126.111 176.403,130.251 176.403,131.267 177.851,132.715 190.627,132.715 191.811,131.531 P4_U2.28@191.811,128.047 ; U4_U2.2@162.941,128.016 164.719,128.016 164.795,128.092 ; 164.719,126.746 164.795,126.822 C31_U2.2@164.795,132.613 ; P4_U2.28@191.719,127.955 P4_U2.28@191.811,128.047
II_FLT_U1: R46_U1.1 U4_U1.7 | length 9.8
  Top Layer w0.508: R46_U1.1@102.26,123.114 102.463,123.317 103.987,123.317 104.546,123.876 104.546,126.467 106.172,128.092 U4_U1.7@108.433,128.092
II_FLT_U2: R46_U2.1 U4_U2.7 | length 47.5
  Top Layer w0.381: U4_U2.7@156.794,128.016 159.563,128.016 v1(160.071,127.508) ; v1(175.539,127.254) 177.47,127.254 179.845,124.879 179.895,124.879 180.378,124.396 180.378,124.346 180.378,121.856 180.975,121.26 180.975,119.659 181.661,118.974 193.98,118.974 R46_U2.1@195.555,120.548
  Bottom Layer w0.381: v1(160.071,127.508) 162.636,124.943 173.228,124.943 v1(175.539,127.254) v1@175.539,127.279
ISO_+5V_U1: C29_U1.2 C30_U1.2 R40_U1.2 U14_U1.1 V1_U1.2 | length 85.7
  Top Layer w0.508: U14_U1.1@99.949,109.372 v1(101.676,109.372) ; V1_U1.2@102.006,112.116 102.006,113.03 v1@102.095,113.119
  Top Layer w1.016: R40_U1.2@34.366,98.958 34.366,105.156 38.43,109.22 66.091,109.22 69.139,106.172 99.466,106.172 99.949,106.655 U14_U1.1@99.949,109.372 ; v1@102.006,113.03 C30_U1.2@102.006,114.3
  Bottom Layer w0.508: v1(101.676,109.372) 102.057,109.753 v1@102.057,113.233
  other v1: 101.981,113.106
ISO_+5V_U2: C29_U2.2 C30_U2.2 R40_U2.2 U14_U2.1 V1_U2.2 | length 169.1
  Top Layer w1.27: v3(141.961,87.655) 141.961,89.459 C30_U2.2@141.859,89.56 C29_U2.2@144.12,89.56 ; V1_U2.2@142.9,95.529 142.951,95.58 v3(142.951,98.781) 144.424,98.781 144.501,98.857
  Top Layer w2.032: v3(207.162,26.187) 207.67,25.679 209.753,25.679 211.912,23.52 211.912,11.379 213.436,9.855 R40_U2.2@223.088,9.855
  Bottom Layer w1.27: v3(141.961,87.655) 143.637,87.655 143.739,87.554 ; v3(142.951,98.781) 142.875,98.704 142.875,94.259 143.739,93.396 143.739,87.554 ; v3(207.162,26.187) 205.511,27.838 200.203,27.838 199.441,28.6 191.592,28.6 189.408,28.6 180.772,37.236 156.337,37.236 154.813,38.76 144.755,38.76 143.739,39.776 143.739,87.554
ISO_+15V_U1: C5_U1.1 C6_U1.1 C7_U1.2 C8_U1.2 C9_U1.2 C10_U1.2 C11_U1.2 C24_U1.1 C25_U1.2 C41_U1.1 C42_U1.1 C43_U1.1 C44_U1.1 C49_U1.1 C50_U1.1 C51_U1.1 C52_U1.1 C66_U1.1 C67_U1.1 C68_U1.1 C103_U1.1 D1_U1.1 D6_U1.1 D8_U1.2 D11_U1.1 D16_U1.1 L2_U1.2 P2_U1.1 P4_U1.1 P4_U1.16 R17_U1.1 U3_U1.2 U6_U1.11 U9_U1.11 U11_U1.11 | length 276.9
  Top Layer w1.016: P4_U1.1@44.374,128.047 44.374,129 P4_U1.16@45.326,129.952 ; C103_U1.1@53.873,96.291 U11_U1.11@57.549,96.291 ; C52_U1.1@53.95,65.049 54.229,65.329 54.966,65.329 ; C43_U1.1@54.305,37.211 54.61,37.516 U6_U1.11@57.752,37.516 ; 54.305,44.145 C41_U1.1@54.432,44.272 ; C66_U1.1@54.966,103.48 59.309,103.48 D16_U1.1@60.122,102.667 ; 54.991,65.354 54.966,65.329 ; C49_U1.1@54.991,72.288 59.741,72.288 D11_U1.1@60.655,71.374 ; U9_U1.11@57.651,65.329 54.966,65.329
  Top Layer w1.27: C24_U1.1@2.667,100.457 C24_U1.1@2.718,100.508 ; P2_U1.1@3.835,117.602 2.667,117.602 1.27,116.205 1.27,101.575 2.337,100.508 C24_U1.1@2.718,100.508 ; U3_U1.2@10.135,100.508 C24_U1.1@2.718,100.508
  Top Layer w1.524: P2_U1.1@3.835,117.602 3.886,117.551 C5_U1.1@11.125,117.551 ; C5_U1.1@11.176,117.602 C5_U1.1@11.125,117.551 ; D1_U1.1@19.025,117.551 C5_U1.1@11.125,117.551 ; 44.374,113.259 44.374,129 ; 44.374,129.005 P4_U1.16@45.324,129.954 ; 46.558,74.93 46.838,74.651 53.696,74.651 54.28,74.066 54.28,65.38 C52_U1.1@54.229,65.329 ; D8_U1.2@50.876,111.151 45.034,111.151 44.374,111.811 44.374,114.173 44.247,114.3 C11_U1.2@18.974,114.3 11.43,114.3 C6_U1.1@11.1,114.63 11.1,117.526 C5_U1.1@11.125,117.551 ; C103_U1.1@53.873,96.52 53.848,96.545 C68_U1.1@53.848,98.679 53.848,103.505 53.924,103.581 53.924,105.131 53.416,105.639 46.838,105.639 v3(46.558,105.359) 46.558,82.067 ; C43_U1.1@54.305,37.211 54.305,44.145 ; L2_U1.2@55.46,82.118 46.609,82.118 46.558,82.067 ; D6_U1.1@60.808,43.561 54.889,43.561 54.305,44.145 ; 46.558,82.067 46.558,49.936 48.387,48.108 53.34,48.108 54.305,47.142 54.305,44.145
  Bottom Layer w1.524: P4_U1.1@44.374,128.047 44.374,127.127 46.558,124.943 v3@46.558,105.334
ISO_+15V_U2: C5_U2.1 C6_U2.1 C7_U2.2 C8_U2.2 C9_U2.2 C10_U2.2 C11_U2.2 C24_U2.1 C25_U2.2 C41_U2.1 C42_U2.1 C43_U2.1 C44_U2.1 C49_U2.1 C50_U2.1 C51_U2.1 C52_U2.1 C66_U2.1 C67_U2.1 C68_U2.1 C103_U2.1 D1_U2.1 D6_U2.1 D8_U2.2 D11_U2.1 D16_U2.1 L2_U2.2 P2_U2.1 P4_U2.1 P4_U2.16 R17_U2.1 U3_U2.2 U6_U2.11 U9_U2.11 U11_U2.11 | length 192
  Top Layer w1.016: D6_U2.1@241.427,42.012 C42_U2.1@247.752,42.012 ; D16_U2.1@241.706,98.958 246.939,98.958 246.964,98.933 ; C50_U2.1@242.164,66.904 241.656,67.412 D11_U2.1@241.656,70.561 241.656,74.981 243.078,76.403 U9_U2.11@244.432,76.403 247.98,76.403 248.006,76.378 ; U6_U2.11@244.355,47.904 247.523,47.904 C44_U2.1@248.26,48.641 C43_U2.1@248.26,46.482 248.26,42.52 C42_U2.1@247.752,42.012 ; U11_U2.11@244.432,104.902 247.675,104.902 C68_U2.1@247.929,105.156 C103_U2.1@247.929,102.972 247.929,100.762 ; C66_U2.1@246.964,97.841 246.964,98.933 ; C42_U2.1@247.218,41.478 C42_U2.1@247.752,42.012 ; C49_U2.1@247.828,72.923 247.828,71.552 248.031,71.349 257.353,71.349 257.835,70.866 ; C49_U2.1@247.98,73.101 C51_U2.1@247.98,75.794 ; C51_U2.1@248.107,75.54 C52_U2.1@248.107,77.749 ; 254.66,95.402 248.641,95.402 247.929,96.114 247.929,100.762 ; 246.964,98.933 246.964,99.797 247.929,100.762
  Top Layer w1.27: P4_U2.1@215.623,129.952 215.623,128.999 P4_U2.16@214.671,128.047 214.671,125.171 217.459,125.171 D8_U2.2@219.278,123.352 ; U3_U2.2@243.815,13.386 247.701,13.386 247.828,13.259
  Top Layer w1.524: R17_U2.1@246.507,13.157 246.609,13.259 247.828,13.259 257.505,13.259 258.857,14.611 258.857,29.23 257.912,30.175 ; C42_U2.1@247.218,41.478 247.218,39.827 247.955,39.091 255.803,39.091 257.302,37.592 ; 258.267,27.661 258.806,27.122
  Top Layer w2.032: 215.316,125.908 218.161,125.908 220.717,123.352 ; D8_U2.2@219.278,123.352 220.717,123.352 ; 225.323,123.352 220.717,123.352 ; 255.448,114.605 254.254,115.799 L2_U2.2@245.047,115.799 245.047,121.934 243.629,123.352 220.717,123.352 ; P2_U2.1@255.956,27.915 258.013,27.915 258.267,27.661
ISO_+15VD_U1: C72_U1.1 C73_U1.1 C106_U1.1 C107_U1.1 C108_U1.1 C109_U1.1 C110_U1.1 C111_U1.1 C112_U1.1 C113_U1.1 L2_U1.1 U6_U1.3 U9_U1.3 U11_U1.3 | length 117.8
  Top Layer w1.016: 64.491,92.507 64.516,92.481 U11_U1.3@68.199,92.481 ; v4@64.643,61.493 64.668,61.519 U9_U1.3@68.301,61.519 ; 64.745,33.401 65.049,33.706 U6_U1.3@68.402,33.706
  Top Layer w1.524: L2_U1.1@60.96,82.118 C112_U1.1@64.44,82.118 ; C111_U1.1@64.491,79.604 64.491,92.507 v4(64.491,93.726) ; v4@64.643,61.493 C106_U1.1@64.643,56.49 64.643,51.791 C109_U1.1@64.668,51.765 ; C113_U1.1@64.77,22.149 C110_U1.1@64.77,24.536 64.77,33.376
  Bottom Layer w1.524: v4(64.491,93.726) 64.465,93.701 64.465,75.413 64.465,25.959 64.643,25.781 64.668,25.806
  other v4: 64.618,26.543 64.643,61.443
ISO_+15VD_U2: C72_U2.1 C73_U2.1 C106_U2.1 C107_U2.1 C108_U2.1 C109_U2.1 C110_U2.1 C111_U2.1 C112_U2.1 C113_U2.1 L2_U2.1 U6_U2.3 U9_U2.3 U11_U2.3 | length 90.9
  Top Layer w0.762: U11_U2.3@233.782,108.712 v3@237.236,108.712
  Top Layer w1.016: U6_U2.3@233.705,51.714 236.195,51.714 236.245,51.765 ; U9_U2.3@233.782,80.213 237.261,80.213 v3@237.287,80.188
  Top Layer w1.524: 236.195,51.714 236.22,51.689 236.779,51.689 237.185,52.095 v3@237.185,65.913 ; C72_U2.1@236.703,118.466 237.185,118.466 237.261,118.389 C111_U2.1@237.261,115.799 ; C111_U2.1@236.982,115.799 C111_U2.1@237.261,115.799 ; v3(237.236,108.661) 237.236,108.636 237.261,108.661 C111_U2.1@237.261,115.799 ; v3@237.287,80.188 237.592,80.493 C113_U2.1@237.592,89.687 ; L2_U2.1@239.319,115.799 C111_U2.1@237.261,115.799
  Bottom Layer w1.524: 237.185,64.668 237.236,64.719 v3(237.236,108.661)
  other v3: 237.236,65.913 237.363,80.264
